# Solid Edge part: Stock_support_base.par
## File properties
Title: Stock Support Base
Author: vicky raina
Template: Normal.par
Last saved by: Robert a Rhodes jr
Revision: 17
Application: Solid Edge
Material: aluminum
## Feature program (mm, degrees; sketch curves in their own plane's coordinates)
sketch for "unnamed RevolvedProtrusion 1" plane through (0, 0, 0) normal (0, -1, 0) x-axis (1, 0, 0)
  line (0, 29.2468) -> (71.7103, 29.2468)
  line (71.7103, 29.2468) -> (71.7103, 19.7218)
  line (71.7103, 19.7218) -> (165.1, -256.5032)
  line (165.1, -256.5032) -> (215.9, -256.5032)
  line (215.9, -256.5032) -> (215.9, -281.9032)
  line (215.9, -281.9032) -> (156.9298, -281.9032)
  line (156.9298, -281.9032) -> (85.052, -69.3053)
  arc centre (73.021, -73.3729) radius 12.7 from (60.325, -73.0538) to (85.052, -69.3053) cw
  line (60.325, -73.0538) -> (57.15, -199.3532)
  line (57.15, -199.3532) -> (0, -199.3532)
  line (0, 29.2468) -> (0, -199.3532)
revolve "unnamed RevolvedProtrusion 1" add full turn 360 deg
sketch for "unnamed Hole 1" plane through (0, 0, 29.2468) normal (0, 0, 1) x-axis (1, 0, 0)
  hole centre (0, 0) bore radius 38.1
hole "unnamed Hole 1" through
sketch for "unnamed Protrusion 1" plane through (0, 0, -256.5032) normal (0, 0, 1) x-axis (0, 1, 0)
  arc centre (0, -119.2664) radius 41.0756 from (-18.7686, -155.8034) to (18.7686, -155.8034) ccw
  line (-18.7686, -197.1314) -> (-18.7686, -155.8034)
  arc centre (0, -197.1314) radius 18.7686 from (18.7686, -197.1314) to (-18.7686, -197.1314) cw
  line (18.7686, -197.1314) -> (18.7686, -155.8034)
extrude "unnamed Protrusion 1" add finite 12.7 along +normal
sketch for "unnamed Hole 2" plane through (187.8036, 0, -243.8032) normal (0, 0, 1) x-axis (1, 0, 0)
hole "unnamed Hole 2" through
fillet "unnamed Round 1"
pattern "unnamed Pattern 1" of "unnamed Protrusion 1", "unnamed Hole 2", "unnamed Round 1"
pattern "unnamed Pattern 2"
sketch for "unnamed Protrusion 2" plane through (0, -134.62, 0) normal (0, -1, 0) x-axis (1, 0, 0)
  circle centre (0, -2.5032) radius 19.05
extrude "unnamed Protrusion 2" add
adv blend "unnamed AdvBlend 1"
sketch for "unnamed Protrusion 3" plane through (0, -134.62, -2.5032) normal (0, -1, 0) x-axis (1, 0, 0)
  circle centre (0, -3.81) radius 22.225
extrude "unnamed Protrusion 3" add finite 9.525 along +normal
mirror "unnamed Mirror 1" of "unnamed Protrusion 3", "unnamed AdvBlend 1", "unnamed Protrusion 2" about plane through (0, 0, 0) normal (0, -1, 0)
extrude "unnamed Protrusion 4" add
adv blend "unnamed AdvBlend 2"
extrude "unnamed Protrusion 5" add finite 9.525
sketch for "unnamed Protrusion 6" plane through (104.775, 0, 0) normal (1, 0, 0) x-axis (0, 1, 0)
  circle centre (0, -167.6032) radius 19.05
extrude "unnamed Protrusion 6" add finite 41.275 along +normal
sketch for "unnamed Hole 3" plane through (146.05, 0, -167.6032) normal (1, 0, 0) x-axis (0, 1, 0)
  hole centre (0, 0) bore radius 7.9375
hole "unnamed Hole 3" through
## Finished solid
Body 1: solid body, 54 faces, 95 edges, 41 vertices.
  Faces by surface: plane 26, cylinder 19, torus 4, cone 3, blend 2
  Edges by curve: circle 57, intersection 20, line 18
Bounding box of the edges (mm; curved faces can reach further): 431.800 x 431.800 x 311.150, from (-215.9, -215.9, -281.9032) to (215.9, 215.9, 29.2468).
Cylindrical faces by radius (mm): R7.9375 x1, R11.1125 x3, R15.875 x3, R18.7686 x3, R19.05 x4, R22.225 x2, R38.1 x1, R71.7103 x1, R215.9 x1
Conical faces (half-angle, radius in mm at the cone's reference point): 1.44 deg R60.325 x1, 18.68 deg R71.7103 x1, 18.68 deg R156.9298 x1
Toroidal faces (ring radius, tube radius in mm): R73.021 r12.7 x1, R163.0843 r3.175 x3
Planar faces by outward normal: +x 1, +y 4, +z 10, -x 1, -y 4, -z 2, oblique 4
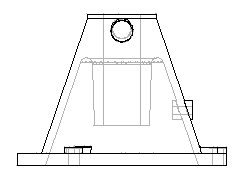
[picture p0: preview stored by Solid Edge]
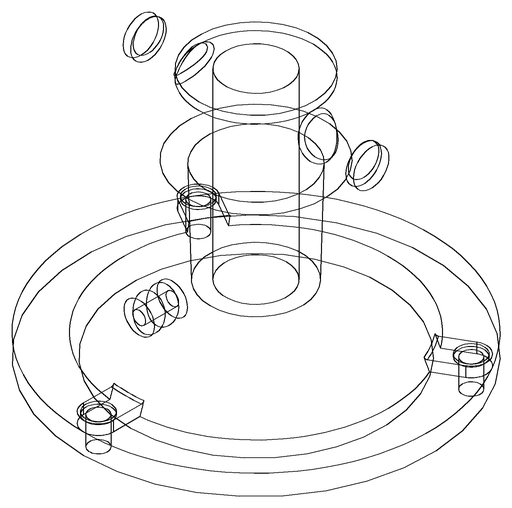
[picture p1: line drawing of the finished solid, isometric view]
